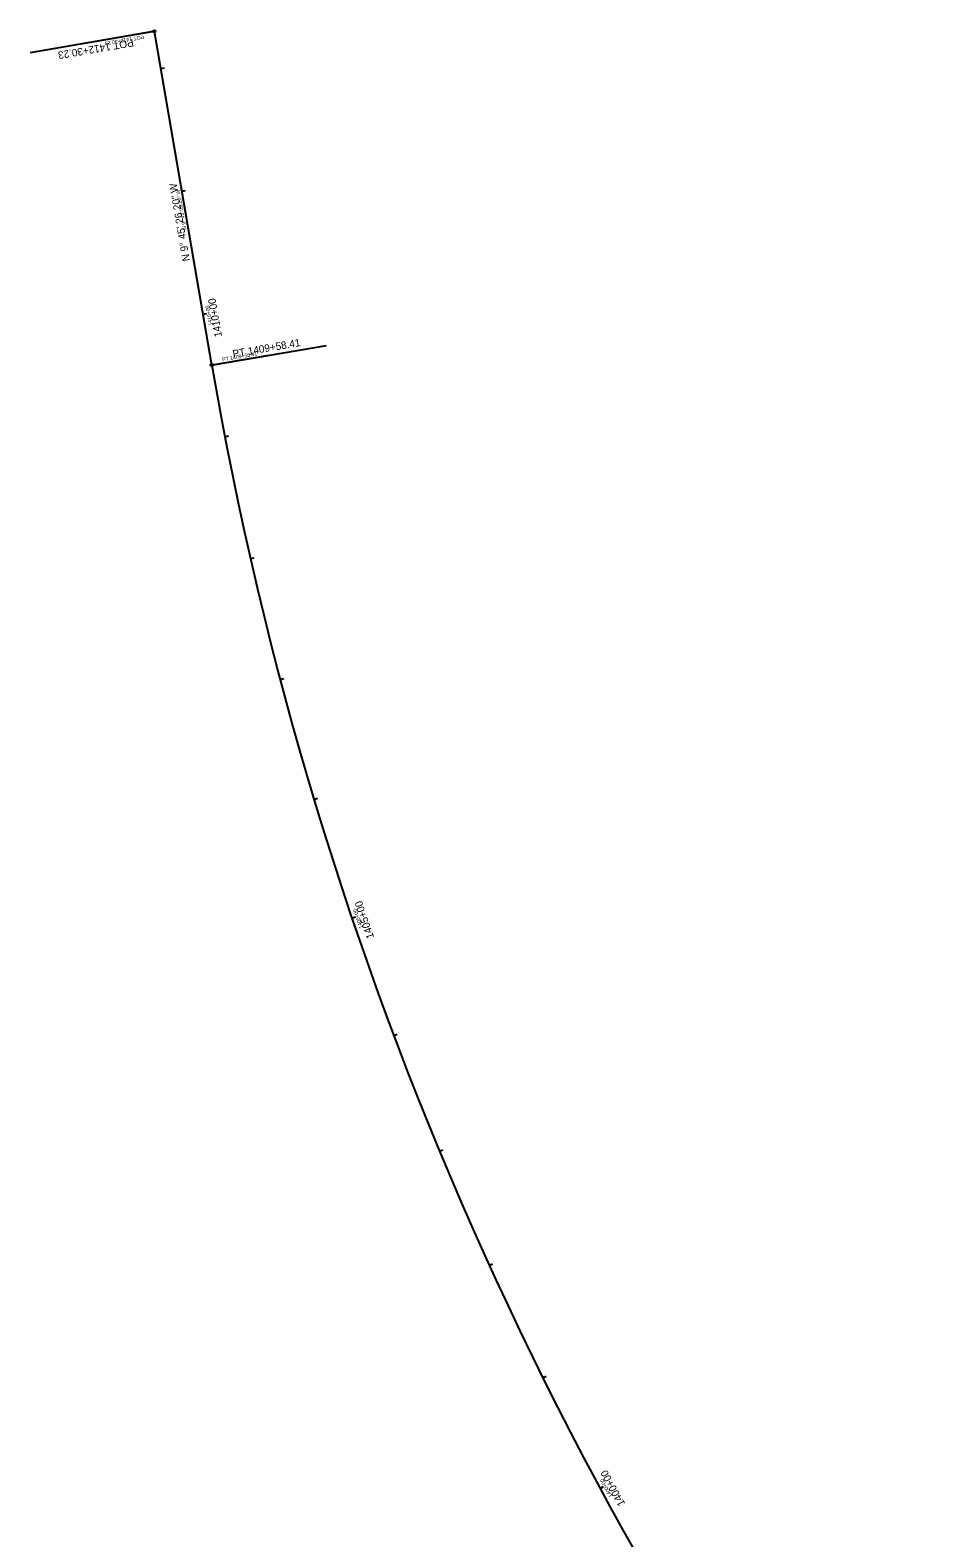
# Model space of a CAD drawing. Extents: x 2252205 to 2259955, y 13788514 to 13798103.
# Drawn here: x 2252205 to 2252933, y 13796893 to 13798103 of the extents above; entities that cross this region are included whole.
import ezdxf

# ---------------------------------------------------------------- set-up
doc = ezdxf.new("R2010")
doc.units = 0
for name, color, linetype in [('GEOM_CENTERLINE_ALIGN', 7, 'Continuous'), ('GEOM_CENTERLINE_PCPT_100', 7, 'Continuous'), ('GEOM_CENTERLINE_PCPT_50', 7, 'Continuous'), ('GEOM_CENTERLINE_STA_100', 7, 'Continuous'), ('GEOM_CENTERLINE_STA_50', 7, 'Continuous')]:
    doc.layers.add(name, color=color, linetype=linetype)

msp = doc.modelspace()

# ---------------------------------------------------------------- linework, layer by layer
at = {"layer": 'GEOM_CENTERLINE_ALIGN'}
msp.add_line((2252351.2, 13797834.5), (2252305.1, 13798102.4), dxfattribs=at)
msp.add_arc((2255258.5, 13798334.5), 2950, 189.7573, 217.9739, dxfattribs=at)
at = {"layer": 'GEOM_CENTERLINE_PCPT_100'}
for p, q in [((2252304.2, 13798102.2), (2252205.4, 13798085.3)), ((2252352.2, 13797834.7), (2252443.2, 13797850.3))]:
    msp.add_line(p, q, dxfattribs=at)
at = {"layer": 'GEOM_CENTERLINE_PCPT_50'}
for p, q in [((2252304.6, 13798102.3), (2252255.3, 13798093.8)), ((2252351.7, 13797834.6), (2252397.2, 13797842.4))]:
    msp.add_line(p, q, dxfattribs=at)
at = {"layer": 'GEOM_CENTERLINE_STA_100'}
for p, q in [((2252310.3, 13798072.6), (2252313.2, 13798073.1)), ((2252327.2, 13797974), (2252330.2, 13797974.6)), ((2252344.2, 13797875.5), (2252347.1, 13797876)), ((2252361.7, 13797777), (2252364.6, 13797777.6)), ((2252382.2, 13797679.2), (2252385.2, 13797679.8)), ((2252406.1, 13797582.1), (2252409, 13797582.8)), ((2252433.2, 13797485.8), (2252436.1, 13797486.7)), ((2252463.6, 13797390.6), (2252466.5, 13797391.5)), ((2252497.2, 13797296.4), (2252500, 13797297.4)), ((2252534, 13797203.4), (2252536.7, 13797204.5)), ((2252573.9, 13797111.7), (2252576.6, 13797112.9)), ((2252616.9, 13797021.4), (2252619.5, 13797022.8)), ((2252662.9, 13796932.6), (2252665.5, 13796934.1))]:
    msp.add_line(p, q, dxfattribs=at)
for centre in [(2252305.1, 13798102.4), (2252351.2, 13797834.5)]:
    msp.add_circle(centre, 1, dxfattribs=at)
at = {"layer": 'GEOM_CENTERLINE_STA_50'}
for p, q in [((2252310.3, 13798072.6), (2252311.7, 13798072.9)), ((2252327.2, 13797974), (2252328.7, 13797974.3)), ((2252344.2, 13797875.5), (2252345.6, 13797875.7)), ((2252361.7, 13797777), (2252363.1, 13797777.3)), ((2252382.2, 13797679.2), (2252383.7, 13797679.5)), ((2252406.1, 13797582.1), (2252407.5, 13797582.5)), ((2252433.2, 13797485.8), (2252434.7, 13797486.3)), ((2252463.6, 13797390.6), (2252465, 13797391)), ((2252497.2, 13797296.4), (2252498.6, 13797296.9)), ((2252534, 13797203.4), (2252535.4, 13797204)), ((2252573.9, 13797111.7), (2252575.2, 13797112.3)), ((2252616.9, 13797021.4), (2252618.2, 13797022.1)), ((2252662.9, 13796932.6), (2252664.2, 13796933.4))]:
    msp.add_line(p, q, dxfattribs=at)
for centre in [(2252305.1, 13798102.4), (2252351.2, 13797834.5)]:
    msp.add_circle(centre, 0.5, dxfattribs=at)

# ---------------------------------------------------------------- texts
at = {"layer": 'GEOM_CENTERLINE_PCPT_100'}
for s, rotation, p in [('POT 1412+30.23', 189.7573, (2252287.9, 13798096.4)), ('PT 1409+58.41', 9.7573, (2252368.4, 13797840.5))]:
    msp.add_text(s, height=6, rotation=rotation, dxfattribs=at).set_placement(p)
at = {"layer": 'GEOM_CENTERLINE_PCPT_50'}
for s, rotation, p in [('POT 1412+30.23', 189.7573, (2252296.5, 13798099.4)), ('PT 1409+58.41', 9.7573, (2252359.8, 13797837.5))]:
    msp.add_text(s, height=3, rotation=rotation, dxfattribs=at).set_placement(p)
at = {"layer": 'GEOM_CENTERLINE_STA_100'}
for s, rotation, p in [('N 9%%d 45\' 26.20" W', 99.7573, (2252333.7, 13797918.4)), ('1410+00', 99.7573, (2252359.4, 13797857.5)), ('1405+00', 108.6606, (2252481.5, 13797375.1)), ('1400+00', 118.3717, (2252683.1, 13796920.4))]:
    msp.add_text(s, height=6, rotation=rotation, dxfattribs=at).set_placement(p)
at = {"layer": 'GEOM_CENTERLINE_STA_50'}
for s, rotation, p in [('N 9%%d 45\' 26.20" W', 99.7573, (2252331, 13797943.4)), ('1410+00', 99.7573, (2252351.8, 13797866.5)), ('1405+00', 108.6606, (2252472.6, 13797382.8)), ('1400+00', 118.3717, (2252673, 13796926.5))]:
    msp.add_text(s, height=3, rotation=rotation, dxfattribs=at).set_placement(p)

doc.saveas('drawing.dxf')
